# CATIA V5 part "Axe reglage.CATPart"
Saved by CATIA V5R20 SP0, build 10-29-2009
Part number: Axe reglage
Bounding box of the stored display mesh (mm): x -10 to 10, y 182.808 to 192.808, z 161.877 to 171.857
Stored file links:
  C:\Users\thinkmotion1\Desktop\Khaled_IAO_Pack2\IAO_2010_1412_jclement\Non_Optimise\Axe reglage.CATPart
  C:\Users\thinkmotion1\Desktop\Khaled_IAO_Pack2\IAO_2010_1412_jclement\Non_Optimise\Synthese IAO_2.CATProduct
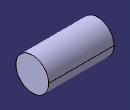
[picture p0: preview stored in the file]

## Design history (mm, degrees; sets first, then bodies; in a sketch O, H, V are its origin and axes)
Set1
  DatumCurve1: linked copy from another document
Body1 (main body)
  Sketch1 on yz-plane, origin (0, 0, 0), H (0, 1, 0), V (0, 0, 1)
    circle A1 centre (187.808, 166.8667) radius 5
    reference projected circle E1 centre (187.808, 166.8667) radius 5 from edge of DatumCurve1
    coincidence: A1 E1
  Pad1: profile Sketch1, direction (1, 0, 0), length 10, mirrored extent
